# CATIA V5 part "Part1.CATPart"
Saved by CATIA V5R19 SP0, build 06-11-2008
Part number: Part1
Bounding box of the stored display mesh (mm): x -30 to 68.928, y -435.613 to 219.055, z -12.333 to 56.576
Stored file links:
  D:\thinkmotion-MPB\Dropbox\CIAO82010_JCF\BELAZOUZ\548-belazouz\Part1.CATPart
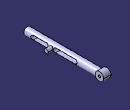
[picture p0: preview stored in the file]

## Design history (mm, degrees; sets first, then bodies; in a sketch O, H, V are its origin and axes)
Body1 (main body)
  Sketch1 on yz-plane, origin (0, 0, 0), H (0, 1, 0), V (0, 0, 1)
    line L1 (164.3871, 20.7358) -> (-435.6129, 20.7358)
    line L2 (164.3871, 20.7358) -> (164.3871, -9.2642)
    line L3 (164.3871, -9.2642) -> (-435.6129, -9.2642)
    line L4 (-435.6129, -9.2642) -> (-435.6129, 20.7358)
    vertical: L2 V, L4 V
  Shaft1: profile Sketch1, axis Sketch1.L1, angle 360
  Sketch2 on yz-plane, origin (0, 0, 0), H (0, 1, 0), V (0, 0, 1)
    circle A1 centre (184.5966, 22.1176) radius 34.458
  Pad1: profile Sketch2, direction (1, 0, 0), length 30, opposite side length 30
  Sketch3 on start face of Pad1, origin (-30, 192.0296, 21.5755), H (0, 1, 0), V (0, 0, -1)
    point P1 (-7.3891, -1.0058)
  Hole1: placed by Sketch3, at (-30, 184.6405, 22.5814) direction (1, 0, 0), diameter 20, through (limit type 3)
  Sketch4 on yz-plane, origin (0, 0, 0), H (0, 1, 0), V (0, 0, 1)
    construction line L1 (-112.2498, 21.1247) -> (-222.7872, 21.1247)
    line L2 (-112.2498, 5.1453) -> (-222.7872, 5.1453)
    line L3 (-222.7872, 37.1042) -> (-112.2498, 37.1042)
    arc A1 centre (-222.7872, 21.1247) radius 15.9794 from (-222.7872, 5.1453) to (-222.7872, 37.1042) cw
    arc A2 centre (-112.2498, 21.1247) radius 15.9794 from (-112.2498, 37.1042) to (-112.2498, 5.1453) cw
    distance L1 L2 = 15.9794
    distance L3 L2 = 31.532
    horizontal: L1 H
    tangency: A1 L2, A2 L2, A1 L3, A2 L3
  Sketch5 on yz-plane, origin (0, 0, 0), H (0, 1, 0), V (0, 0, 1)
    construction line L1 (-177.6992, 22.5774) -> (-16.2563, 22.5774)
    line L2 (-177.6992, 38.9653) -> (-16.2563, 38.9653)
    line L3 (-16.2563, 6.1894) -> (-177.6992, 6.1894)
    arc A1 centre (-16.2563, 22.5774) radius 16.3879 from (-16.2563, 38.9653) to (-16.2563, 6.1894) cw
    arc A2 centre (-177.6992, 22.5774) radius 16.3879 from (-177.6992, 6.1894) to (-177.6992, 38.9653) cw
    distance L1 L2 = 16.3879
    horizontal: L1 H
    tangency: A1 L2, A2 L2, A1 L3, A2 L3
  Pocket1: profile Sketch4, direction (-1, 0, 0), length 30, deactivated
  Pocket2: profile Sketch5, direction (-1, 0, 0), through (limit type 3), opposite side length 50
  Sketch6 on yz-plane, origin (0, 0, 0), H (0, 1, 0), V (0, 0, 1)
    circle A1 centre (-212.2387, 21.4877) radius 15.766
    reference projected line E1 (-16.2563, 6.1894) -> (-177.6992, 6.1894) from edge [face of Pocket2 from Sketch5.L3 | face of Shaft1 from Sketch1.L3]
    reference projected line E2 (-177.6992, 38.9653) -> (-16.2563, 38.9653) from edge [face of Pocket2 from Sketch5.L2 | face of Shaft1 from Sketch1.L3]
    radius A1 = 15.766
    distance E1 E2 = 32.7759 (reference)
  Pad2: profile Sketch6, direction (1, 0, 0), length 68.928
  Sketch7 on yz-plane, origin (0, 0, 0), H (0, 1, 0), V (0, 0, 1)
    construction line L1 (-252.1222, 21.4871) -> (-361.6774, 21.4871)
    line L2 (-252.1222, 5.7211) -> (-361.6774, 5.7211)
    line L3 (-361.6774, 37.2531) -> (-252.1222, 37.2531)
    arc A1 centre (-361.6774, 21.4871) radius 15.766 from (-361.6774, 5.7211) to (-361.6774, 37.2531) cw
    arc A2 centre (-252.1222, 21.4871) radius 15.766 from (-252.1222, 37.2531) to (-252.1222, 5.7211) cw
    distance L3 L2 = 31.532
    horizontal: L1 H
    tangency: A1 L2, A2 L2, A1 L3, A2 L3
  Pocket3: profile Sketch7, direction (-1, 0, 0), through (limit type 3), opposite side through (limit type 3)
  Point1: type OnSurface, Support end face of Pad2, Length 0, Direction (-0.6904, 0.6414, 0.3347)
